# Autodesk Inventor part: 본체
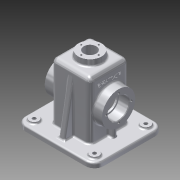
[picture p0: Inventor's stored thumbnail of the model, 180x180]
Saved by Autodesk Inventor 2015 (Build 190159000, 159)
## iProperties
Created: 2016-02
Part Number: 본체
Material: 알루미늄 6061
Document SubType Name: Modeling
Designer: Administrator
Density: 2.7 g/cm^3
Appearance: 알루미늄 - 평지
Mass: 783.577 g
Surface Area: 892.209 cm^2
Volume: 290.214 cm^3
Author: Administrator
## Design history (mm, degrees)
sketch "스케치1"
  geometry: C1 r 27.5 at (0, 0); 1 further point
  constraints: 1 centre point, 1 coincident
  dimensions: "d0" = 55 diameter of C1
extrude "돌출1" new body sketch "스케치1" stored distance "d1" = 95; taper "d2" = 0 deg
node "작업 평면1"
sketch "스케치2"
  geometry: L1 (-65, -57.5)-(65, -57.5); L2 (65, -57.5)-(65, 57.5); L3 (65, 57.5)-(-65, 57.5); L4 (-65, 57.5)-(-65, -57.5); L5 (-65, -57.5)-(65, 57.5); L6 (65, -57.5)-(-65, 57.5); 1 further point
  constraints: 12 end point, 2 midpoint, 2 parallel, 1 horizontal, 1 perpendicular
  dimensions: "d4" = 115 distance between parallel lines of L1 L3; "d5" = 130 distance between parallel lines of L4 L2
extrude "돌출2" join sketch "스케치2" distance "d6" = 8; taper "d7" = 0 deg
sketch "스케치3"
  geometry: L1 (65, 57.5)-(-65, 57.5) reference; L2 (-65, 57.5)-(-65, -57.5) reference; C1 r 7.5 at (-50, 42.5); C2 r 7.5 at (50, 42.5); C3 r 7.5 at (-50, -42.5); C4 r 7.5 at (50, -42.5); 1 further point
  constraints: 4 centre point, 1 horizontal, 1 vertical, 6 other
  dimensions: "d8" = 15 diameter of C1; "d11" = 100 distance of C1.centre C2.centre; "d14" = 85 distance of C1.centre C3.centre; "d17" = 50 horizontal distance of C1.centre point (0, 0); "d18" = 42.5 vertical distance of point (0, 0) C2.centre
extrude "돌출3" join sketch "스케치3" distance "d19" = 3; taper "d20" = 0 deg
fillet "모깎기1" dims "d21" = 15
sketch "스케치4"
  geometry: L1 (-32.5, -50)-(32.5, -50); L2 (32.5, -50)-(32.5, 50); L3 (32.5, 50)-(-32.5, 50); L4 (-32.5, 50)-(-32.5, -50); L5 (-32.5, -50)-(32.5, 50); L6 (32.5, -50)-(-32.5, 50); L7 (50, -53)-(-50, -53) reference; 1 further point
  constraints: 12 end point, 2 midpoint, 2 parallel, 1 horizontal, 1 perpendicular
  dimensions: "d22" = 103 distance between parallel lines of L7 L3; "d23" = 65 distance between parallel lines of L4 L2
extrude "돌출4" join sketch "스케치4" stored distance "d24" = 65; taper "d25" = 0 deg
node "작업 평면2"
sketch "스케치9"
  geometry: L1 (60, -52.5)-(-60, -52.5); L2 (-60, -52.5)-(-60, 52.5); L3 (-60, 52.5)-(60, 52.5); L4 (60, 52.5)-(60, -52.5); L5 (60, -52.5)-(-60, 52.5); L6 (-60, -52.5)-(60, 52.5); L7 (-65, 42.5)-(-65, -42.5) reference; L8 (50, 57.5)-(-50, 57.5) reference; 1 further point
  constraints: 12 end point, 2 midpoint, 2 parallel, 1 horizontal, 1 perpendicular
  dimensions: "d43" = 5 distance between parallel lines of L7 L2; "d44" = 5 distance between parallel lines of L8 L3
extrude "돌출7" join sketch "스케치9" distance "d45" = 2; taper "d46" = 0 deg
sketch "스케치10"
  geometry: L1 (17.5, 75)-(82.5, 75) reference; L2 (82.5, 75)-(82.5, 10) reference; L3 (82.5, 10)-(17.5, 10) reference; L4 (17.5, 10)-(17.5, 75) reference; L5 (-15, 85)-(-15, 0) reference; L6 (0, -15)-(100, -15) reference; L7 (115, 0)-(115, 85) reference; L8 (100, 100)-(0, 100) reference; C1 r 7.5 at (0, 0) reference; C2 r 7.5 at (0, 85) reference; C3 r 7.5 at (100, 85) reference; C4 r 7.5 at (100, 0) reference; C5 r 7.5 at (100, 0) reference; A1 r 15 centre (0, 85) between (0, 100) and (-15, 85) reference; A2 r 15 centre (0, 0) between (-15, 0) and (0, -15) reference; A3 r 15 centre (100, 0) between (100, -15) and (115, 0) reference; A4 r 15 centre (100, 85) between (115, 85) and (100, 100) reference; 5 further points
  constraints: 4 coincident
hole "구멍3" sketch "스케치10" at (0, 0), (100, 0), (100, 85), (0, 85) diameter "d57" = 6; stored, may be unused: countersink angle "d61" = 90 deg, drill point angle "d63" = 118 deg; dims "d58" = 6, "d59" = 4, "d60" = 2, "d62" = 8
sketch "스케치13"
  geometry: C1 r 20 at (32.5, 32.5); 1 further point
  constraints: 1 centre point, 1 coincident
  dimensions: "d66" = 40 diameter of C1
extrude "돌출8" join sketch "스케치13" distance "d67" = 10; taper "d68" = 0 deg
feature "면 기울기2" dims angle "d69" = 5 deg
hole "구멍4" diameter "d72" = 35; stored, may be unused: countersink angle "d76" = 90 deg, drill point angle "d78" = 0 deg; dims "d70" = 10, "d71" = 10, "d73" = 6, "d74" = 4, "d75" = 2, "d77" = 17
hole "구멍5" diameter "d81" = 30; stored, may be unused: countersink angle "d85" = 90 deg, drill point angle "d87" = 0 deg; dims "d79" = 10, "d80" = 10, "d82" = 6, "d83" = 4, "d84" = 2, "d86" = 17
hole "구멍6" diameter "d90" = 35; stored, may be unused: countersink angle "d94" = 90 deg, drill point angle "d96" = 0 deg; dims "d88" = 10, "d89" = 10, "d91" = 6, "d92" = 4, "d93" = 2, "d95" = 17
sketch "스케치15"
  geometry: L1 (-32.5, 27.5)-(-32.5, 50) reference; L2 (-32.5, 50)-(-20, 50) reference; L3 (-20, 50)-(-19.125, 60) reference; L4 (-19.125, 60)-(19.125, 60) reference; L5 (19.125, 60)-(20, 50) reference; L6 (20, 50)-(32.5, 50) reference; L7 (32.5, 50)-(32.5, 27.5) reference; L8 (32.5, 27.5)-(47.5, 27.5) reference; L9 (47.5, 27.5)-(47.5, 17.5) reference; L10 (47.5, 17.5)-(30.5, 17.5) reference; L11 (30.5, 17.5)-(30.5, 15) reference; L12 (30.5, 15)-(-30.5, 15) reference; L13 (-30.5, 15)-(-30.5, 17.5) reference; L14 (-30.5, 17.5)-(-47.5, 17.5) reference; L15 (-47.5, 17.5)-(-47.5, 27.5) reference; L16 (-47.5, 27.5)-(-32.5, 27.5) reference; L17 (-65, -53)-(-65, -45) reference; L18 (-65, -45)-(-32.5, -45) reference; L19 (-32.5, -45)-(-32.5, -27.5) reference; L20 (-32.5, -27.5)-(-47.5, -27.5) reference; L21 (-47.5, -27.5)-(-47.5, -17.5) reference; L22 (-47.5, -17.5)-(-30.5, -17.5) reference; L23 (-30.5, -17.5)-(-30.5, -15) reference; L24 (-30.5, -15)-(30.5, -15) reference; L25 (30.5, -15)-(30.5, -17.5) reference; L26 (30.5, -17.5)-(47.5, -17.5) reference; L27 (47.5, -17.5)-(47.5, -27.5) reference; L28 (47.5, -27.5)-(32.5, -27.5) reference; L29 (32.5, -27.5)-(32.5, -45) reference; L30 (32.5, -45)-(65, -45) reference; L31 (65, -45)-(65, -53) reference; L32 (65, -53)-(60, -53) reference; L33 (60, -53)-(60, -55) reference; L34 (60, -55)-(-60, -55) reference; L35 (-60, -55)-(-60, -53) reference; L36 (-60, -53)-(-65, -53) reference; L37 (27.5, 45)-(-27.5, 45); L38 (-27.5, 45)-(-27.5, -55); L39 (-27.5, -55)-(27.5, -55); L40 (27.5, -55)-(27.5, 45); 1 further point
  constraints: 8 end point, 2 parallel, 1 horizontal, 1 perpendicular
  dimensions: "d104" = 15 distance between parallel lines of L4 L37; "d105" = 5 distance between parallel lines of L1 L38; "d106" = 0 distance between parallel lines of L34 L39; "d107" = 5 distance between parallel lines of L7 L40
extrude "돌출9" cut sketch "스케치15" stored distance "d101" = 55; taper "d102" = 0 deg
fillet "모깎기3" dims "d108" = 8
fillet "모깎기4" dims "d109" = 8
fillet "모깎기5" dims "d110" = 3
chamfer "모따기1" distance "d111" = 1; stored, may be unused: second distance "d112" = 2, angle "d113" = 45 deg
fillet "모깎기6" dims "d114" = 0.3
sketch "스케치16" dims "d115" = 42
  geometry: C1 r 27.5 at (0, 0) reference; C2 r 18.5 at (0, 0) reference; 5 further points
  constraints: 2 vertical alignment, 1 coincident, 7 other
  dimensions: "d118" = 360 deg dimension on C1.centre point (0, 21) (derived)
hole "구멍7" sketch "스케치16" at (0, 21), (-21, 0), (0, -21), (21, 0) diameter "d120" = 3.242; stored, may be unused: countersink angle "d124" = 90 deg, drill point angle "d126" = 118 deg; dims "d121" = 8, "d122" = 4, "d123" = 2, "d125" = 10
sketch "스케치17" dims "d127" = 42
  geometry: C1 r 27.5 at (0, 0) reference; C2 r 18.5 at (0, 0) reference; 5 further points
  constraints: 2 vertical alignment, 1 coincident, 7 other
  dimensions: "d130" = 360 deg dimension on C1.centre point (0, 21) (derived)
hole "구멍8" sketch "스케치17" at (0, 21), (-21, 0), (0, -21), (21, 0) diameter "d132" = 3.242; stored, may be unused: countersink angle "d136" = 90 deg, drill point angle "d138" = 118 deg; dims "d133" = 8, "d134" = 4, "d135" = 2, "d137" = 10
sketch "스케치18"
  geometry: L1 (-58.808, -47.5)-(-11.41, -47.5); L2 (-45, -57.5)-(-53, -57.5) reference; L3 (-45, -42.5)-(-45, -57.5) reference; L4 (-45, -47.5)-(40.069, -32.5); L5 (42, -32.5)-(-45, -32.5) reference; L6 (40.069, -32.5)-(-45, -32.5); L7 (-45, -32.5)-(-45, -47.5); 1 further point
  constraints: 8 end point, 3 point on line, 2 collinear, 1 horizontal
  dimensions: "d141" = 10 distance between parallel lines of L2 L1; "d142" = 10 deg angle of L1 L4
extrude "돌출10" join sketch "스케치18" stored distance "d143" = 10; taper "d144" = 0 deg
fillet "모깎기9" dims "d147" = 3
sketch "스케치19"
  geometry: C1 r 19.125 at (0, 0) reference; C2 r 10.5 at (0, 0)
  constraints: 1 centre point, 1 coincident
  dimensions: "d148" = 21 diameter of C2
extrude "돌출11" cut sketch "스케치19" stored distance "d149" = 10; taper "d150" = 0 deg
fillet "모깎기10" dims "d151" = 3
fillet "모깎기11" dims "d152" = 3
fillet "모깎기12" dims "d153" = 3
fillet "모깎기13" dims "d154" = 3
sketch "스케치20" dims "d155" = 29
  geometry: C1 r 10.5 at (0, 0) reference; C2 r 19.125 at (0, 0) reference; 5 further points
  constraints: 2 horizontal alignment, 1 coincident, 7 other
  dimensions: "d158" = 360 deg dimension on C1.centre point (-14.5, 0) (derived)
hole "구멍9" sketch "스케치20" at (-14.5, 0), (0, -14.5), (14.5, 0), (0, 14.5) diameter "d160" = 2.459; stored, may be unused: countersink angle "d164" = 90 deg, drill point angle "d166" = 118 deg; dims "d161" = 7, "d162" = 4, "d163" = 2, "d165" = 9
fillet "모깎기14" dims "d167" = 3
sketch "스케치21"
  geometry: L1 (42.5, -25)-(42.5, -55); L2 (27.5, 45)-(27.5, -55) reference; L3 (42.5, -55)-(27.5, -55); L4 (27.5, -25)-(27.5, -55); L5 (-60, -55)-(60, -55) reference; L6 (27.5, -25)-(42.5, -25); 1 further point
  constraints: 8 end point, 2 perpendicular, 2 point on line, 1 collinear, 1 vertical
  dimensions: "d169" = 15 distance between parallel lines of L1 L2; "d170" = 0 distance between parallel lines of L5 L3; "d171" = 30 distance between parallel lines of L3 L6
extrude "돌출12" join sketch "스케치21" stored distance "d172" = 6; taper "d173" = 0 deg
fillet "모깎기15" dims "d174" = 3
fillet "모깎기16" dims "d175" = 3
fillet "모깎기17" dims "d176" = 3
fillet "모깎기18" dims "d177" = 3
node "작업 평면3"
sketch "스케치22"
  geometry: L1 (60, -19.125)-(60, 19.125) reference; 2 further points
  constraints: 1 horizontal alignment, 1 other
  dimensions: "d179" = 26 distance from line of L1 point (34, 0)
feature "엠보싱1" sketch "스케치22" dims "d8" = 15, "d11" = 100, "d14" = 85, "d17" = 50, "d18" = 42.5, "d180" = 0.5, "d181" = 0
fillet "모깎기19" dims "d182" = 3
fillet "모깎기20" dims "d183" = 10
node "솔리드1"
mirror "대칭1"
mirror "대칭2"
node "투영된 루프4"
node "절단 모서리 투영1"
other parameters: "d3" = -53, "d42" = -55
